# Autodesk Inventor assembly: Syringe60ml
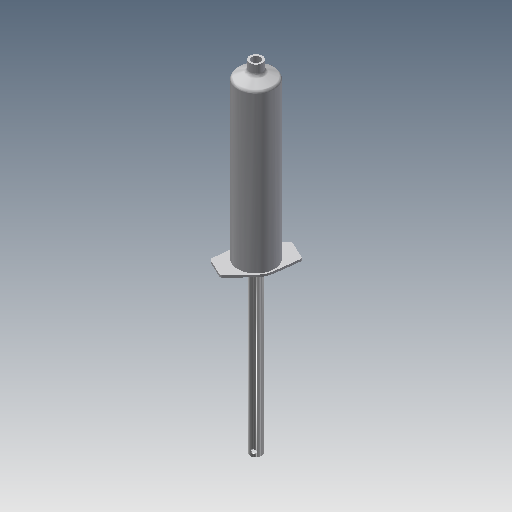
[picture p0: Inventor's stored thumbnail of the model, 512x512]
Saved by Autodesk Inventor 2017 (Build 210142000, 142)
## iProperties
Created: 2018-08
Part Number: Syringe60ml
Document SubType Name: Assembly
Designer: JK
Author: JK
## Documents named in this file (5)
- C:\Users\JK\Documents\Inventor\BioExtruder\Syringe60ml.iam
- C:\Users\JK\Documents\Inventor\BioExtruder\Syringe_60ml_rubber.ipt
- C:\Users\JK\Documents\Inventor\BioExtruder\Syringe_60ml_Exterior.ipt
- C:\Users\JK\Documents\Inventor\BioExtruder\tuboalum.ipt
- C:\Users\JK\Documents\Inventor\BioExtruder\embolo60cc.ipt
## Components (4 placed, 4 different names)
1. Syringe_60ml_rubber:1 — Mate:3, Mate:5
2. Syringe_60ml_Exterior:1 — Mate:3, Mate:7
3. tuboalum:1 — Mate:4, Mate:6
4. embolo60cc:1 — Mate:4, Mate:5, Mate:6, Mate:7
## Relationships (5: Mate 5)
- Mate:3: Syringe_60ml_rubber:1 ↔ Syringe_60ml_Exterior:1
- Mate:4: tuboalum:1 ↔ embolo60cc:1
- Mate:5: Syringe_60ml_rubber:1 ↔ embolo60cc:1
- Mate:6: tuboalum:1 ↔ embolo60cc:1
- Mate:7: Syringe_60ml_Exterior:1 ↔ embolo60cc:1
